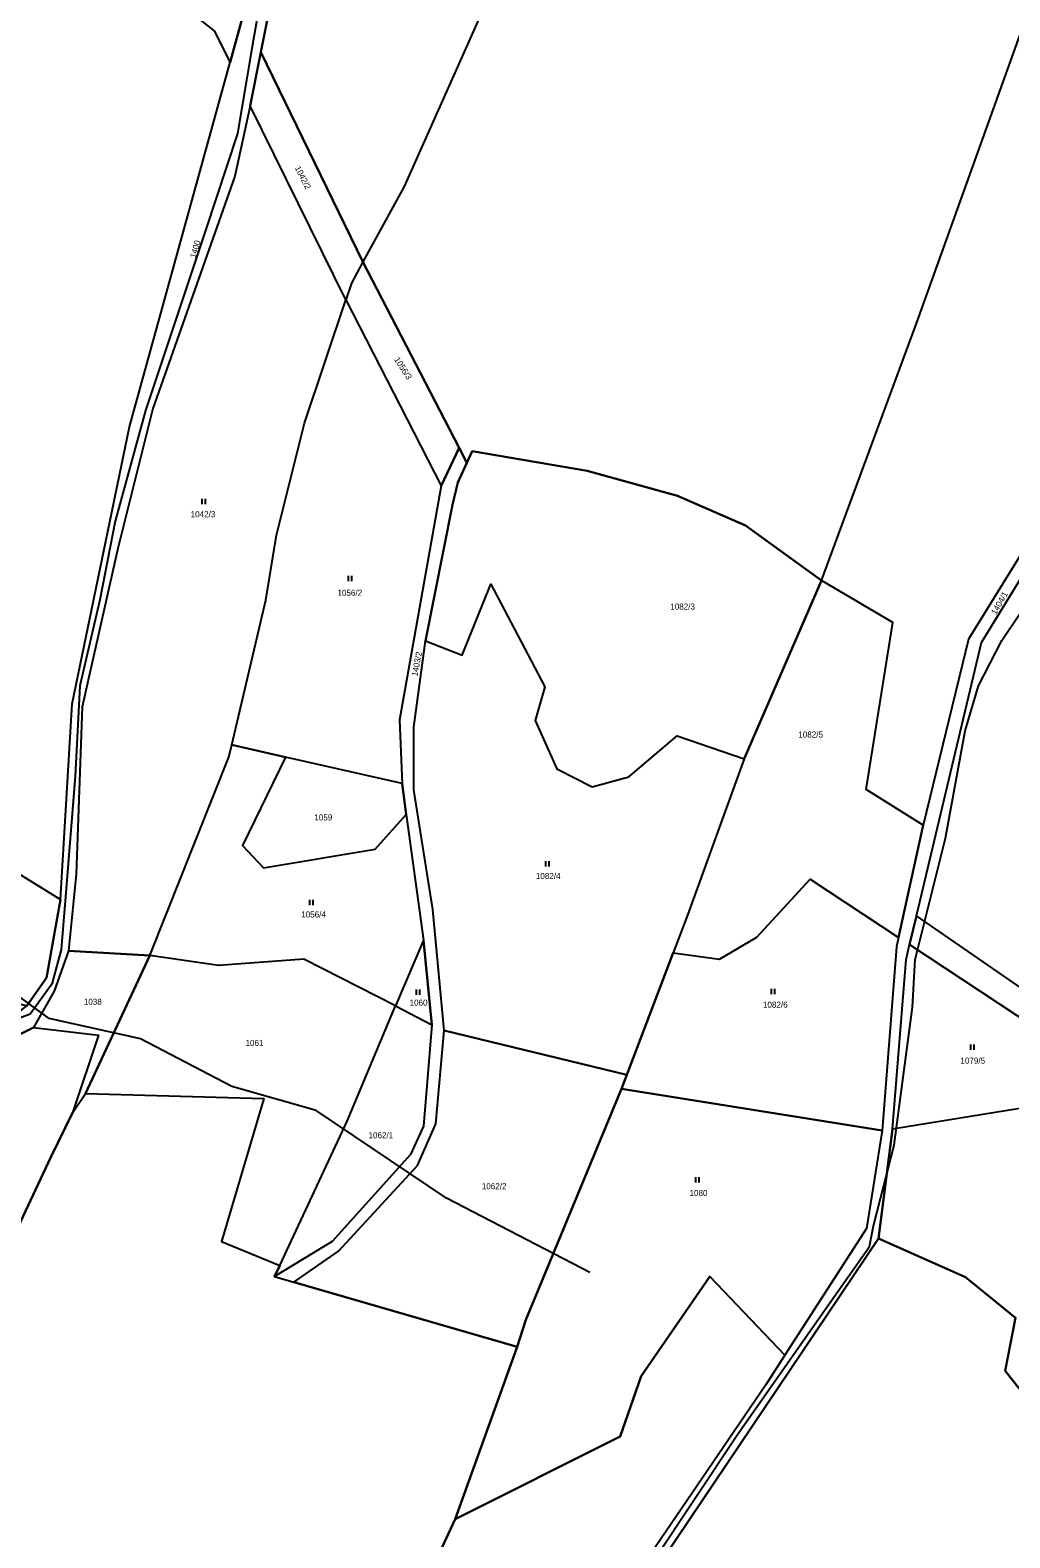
# Model space of a CAD drawing. Extents: x -588699 to -585793, y -1060280 to -1056731.
# Drawn here: x -588096.7 to -587820.9, y -1059020.2 to -1058596 of the extents above; entities that cross this region are included whole.
import ezdxf

# ---------------------------------------------------------------- set-up
doc = ezdxf.new("R2010")
doc.units = 0
for name, color, linetype in [('Druh pozemku', 7, 'Continuous'), ('Parcela nároku', 7, 'Continuous'), ('Vnitřní obvod', 7, 'Continuous'), ('Vnější obvod_k šeření', 7, 'Continuous')]:
    doc.layers.add(name, color=color, linetype=linetype)

msp = doc.modelspace()

# ---------------------------------------------------------------- linework, layer by layer
at = {"layer": 'Druh pozemku'}
for p, q in [((-588048.34, -1058727.85), (-588048.34, -1058729.35)), ((-588047.32, -1058729.35), (-588047.32, -1058727.85)), ((-588007.19, -1058749.54), (-588007.19, -1058751.04)), ((-588006.17, -1058751.04), (-588006.17, -1058749.54)), ((-587951.59, -1058829.77), (-587951.59, -1058831.27)), ((-587950.57, -1058831.27), (-587950.57, -1058829.77)), ((-588018.07, -1058840.65), (-588018.07, -1058842.15)), ((-588017.05, -1058842.15), (-588017.05, -1058840.65)), ((-587988.03, -1058865.91), (-587988.03, -1058867.41)), ((-587987.01, -1058867.41), (-587987.01, -1058865.91)), ((-587888.08, -1058865.71), (-587888.08, -1058867.21)), ((-587887.06, -1058867.21), (-587887.06, -1058865.71)), ((-587832, -1058881.34), (-587832, -1058882.84)), ((-587830.97, -1058882.84), (-587830.97, -1058881.34)), ((-587909.41, -1058918.67), (-587909.41, -1058920.17)), ((-587908.39, -1058920.17), (-587908.39, -1058918.67))]:
    msp.add_line(p, q, dxfattribs=at)
at = {"layer": 'Parcela nároku'}
for points in [[(-588012.84, -1058544.25), (-587965.05, -1058467.76), (-587942.29, -1058493.44), (-587956.18, -1058550.14), (-587968.29, -1058588.22), (-587991.4, -1058639.93), (-588003.03, -1058661.2), (-588031.77, -1058602.2), (-588025, -1058568.22)], [(-588109.84, -1058534.93), (-588036.79, -1058592.04), (-588040.36, -1058604.95), (-588044.66, -1058596.24), (-588112.84, -1058542.38)], [(-588189.32, -1058742.9), (-588190.21, -1058759.8), (-588172.56, -1058777.54), (-588159.73, -1058806.34), (-588132.18, -1058821.5), (-588109.1, -1058827.66), (-588088.15, -1058840.59), (-588084.85, -1058785.48), (-588068.73, -1058707.6), (-588040.36, -1058604.95), (-588044.66, -1058596.24), (-588112.84, -1058542.38), (-588131.02, -1058585.83), (-588144.44, -1058606.7), (-588168.14, -1058675.06)], [(-588031.77, -1058602.2), (-588003.03, -1058661.2), (-588006.27, -1058667.12), (-588007.86, -1058671.88), (-588034.7, -1058617.24)], [(-588072.03, -1058741.84), (-588082.04, -1058786.35), (-588083.73, -1058833.41), (-588085.9, -1058855), (-588062.96, -1058856.3), (-588040.73, -1058800.53), (-588039.91, -1058797.03), (-588030.34, -1058756.33), (-588027.37, -1058738.07), (-588019.46, -1058706.56), (-588007.86, -1058671.88), (-588034.7, -1058617.24), (-588039.05, -1058637.03), (-588062.18, -1058702.41)], [(-587975.92, -1058713.52), (-588003.03, -1058661.2), (-588006.27, -1058667.12), (-588007.86, -1058671.88), (-587980.98, -1058724.18)], [(-588019.46, -1058706.56), (-588007.86, -1058671.88), (-587980.98, -1058724.18), (-587992.71, -1058790.06), (-587992, -1058807.94), (-588024.76, -1058800.48), (-588039.91, -1058797.03), (-588030.34, -1058756.33), (-588027.37, -1058738.07)], [(-587983.65, -1058875.79), (-587985.94, -1058904.34), (-587989.61, -1058912.34), (-588011.67, -1058936.8), (-588027.86, -1058946.66), (-588022.46, -1058948.22), (-588009.91, -1058939.54), (-587987.63, -1058915.45), (-587982.53, -1058903.73), (-587980.17, -1058877.47), (-587983.38, -1058843.42), (-587988.72, -1058809.72), (-587988.72, -1058792.06), (-587985.38, -1058767.81), (-587977.81, -1058729.55), (-587976.33, -1058723.23), (-587973.78, -1058717.71), (-587975.92, -1058713.52), (-587980.98, -1058724.18), (-587992.71, -1058790.06), (-587992, -1058807.94), (-587990.81, -1058816.7), (-587986.01, -1058851.97)], [(-587914.45, -1058726.97), (-587939.88, -1058719.94), (-587972.25, -1058714.41), (-587973.78, -1058717.71), (-587976.33, -1058723.23), (-587977.81, -1058729.55), (-587985.38, -1058767.81), (-587975.04, -1058771.83), (-587967.02, -1058751.85), (-587951.78, -1058780.74), (-587954.54, -1058790.2), (-587948.48, -1058803.84), (-587938.5, -1058808.83), (-587928.16, -1058806.07), (-587914.61, -1058794.48), (-587895.71, -1058801.01), (-587873.98, -1058750.77), (-587895.32, -1058735.33)], [(-587954.54, -1058790.2), (-587948.48, -1058803.84), (-587938.5, -1058808.83), (-587928.16, -1058806.07), (-587914.61, -1058794.48), (-587895.71, -1058801.01), (-587911.64, -1058844.95), (-587915.68, -1058855.57), (-587928.74, -1058889.95), (-587980.17, -1058877.47), (-587983.38, -1058843.42), (-587988.72, -1058809.72), (-587988.72, -1058792.06), (-587985.38, -1058767.81), (-587975.04, -1058771.83), (-587967.02, -1058751.85), (-587951.78, -1058780.74)], [(-587853.86, -1058762.63), (-587873.98, -1058750.77), (-587895.71, -1058801.01), (-587911.64, -1058844.95), (-587915.68, -1058855.57), (-587902.69, -1058857.39), (-587892.19, -1058851.17), (-587877.15, -1058834.81), (-587852.25, -1058851.24), (-587845.33, -1058819.66), (-587861.34, -1058809.6)], [(-588109.1, -1058827.66), (-588088.15, -1058840.59), (-588092.07, -1058862.61), (-588097.6, -1058870.46), (-588109.72, -1058867.96), (-588143.59, -1058855.75), (-588178.69, -1058824), (-588198.5, -1058806.08), (-588211.07, -1058801.26), (-588191.27, -1058761.91), (-588190.21, -1058759.8), (-588172.56, -1058777.54), (-588159.73, -1058806.34), (-588132.18, -1058821.5)], [(-587990.81, -1058816.7), (-587986.01, -1058851.97), (-587993.87, -1058870.52), (-588019.67, -1058857.36), (-588043.64, -1058859.15), (-588062.96, -1058856.3), (-588040.73, -1058800.53), (-588039.91, -1058797.03), (-588024.76, -1058800.48), (-588036.89, -1058825.37), (-588031.03, -1058831.68), (-587999.58, -1058826.39)], [(-587990.81, -1058816.7), (-587992, -1058807.94), (-588024.76, -1058800.48), (-588036.89, -1058825.37), (-588031.03, -1058831.68), (-587999.58, -1058826.39)], [(-587930.23, -1058893.88), (-587928.74, -1058889.95), (-587915.68, -1058855.57), (-587902.69, -1058857.39), (-587892.19, -1058851.17), (-587877.15, -1058834.81), (-587852.25, -1058851.24), (-587852.87, -1058853.92), (-587856.9, -1058905.55)], [(-587804.58, -1058874.64), (-587847.22, -1058845.13), (-587849.15, -1058853.28), (-587804.12, -1058882.99), (-587796.78, -1058895.87), (-587776.67, -1058931.16), (-587774.83, -1058926.17)], [(-588085.9, -1058855), (-588089.94, -1058866.37), (-588095.73, -1058876.62), (-588077.46, -1058878.76), (-588084.75, -1058900.64), (-588081.07, -1058895.13), (-588062.96, -1058856.3)], [(-587986.01, -1058851.97), (-587993.87, -1058870.52), (-587983.65, -1058875.79)], [(-587849.15, -1058853.28), (-587804.12, -1058882.99), (-587796.78, -1058895.87), (-587853.95, -1058905.21), (-587850.15, -1058857.49)], [(-588043.64, -1058859.15), (-588062.96, -1058856.3), (-588081.07, -1058895.13), (-588030.89, -1058896.53), (-588042.81, -1058936.79), (-588026.41, -1058943.57), (-588007.44, -1058902.96), (-587993.87, -1058870.52), (-588019.67, -1058857.36)], [(-587993.87, -1058870.52), (-587983.65, -1058875.79), (-587985.94, -1058904.34), (-587989.61, -1058912.34), (-588011.67, -1058936.8), (-588027.86, -1058946.66), (-588026.41, -1058943.57), (-588007.44, -1058902.96)], [(-587982.53, -1058903.73), (-587980.17, -1058877.47), (-587928.74, -1058889.95), (-587930.23, -1058893.88), (-587957.2, -1058958.88), (-587959.61, -1058966.41), (-588022.46, -1058948.22), (-588009.91, -1058939.54), (-587987.63, -1058915.45)], [(-587977.01, -1059014.9), (-587959.61, -1058966.41), (-587957.2, -1058958.88), (-587930.23, -1058893.88), (-587856.9, -1058905.55), (-587861.28, -1058933.17), (-587884.31, -1058968.74), (-587905.4, -1058946.63), (-587924.68, -1058974.72), (-587930.6, -1058991.62)], [(-587789.32, -1058964.36), (-587792.22, -1058963.13), (-587801.94, -1058917.76), (-587796.24, -1058906.14), (-587796.78, -1058895.87), (-587853.95, -1058905.21), (-587857.94, -1058935.91), (-587833.41, -1058946.87), (-587819.38, -1058958.28), (-587822.27, -1058973.22), (-587812.23, -1058985.89), (-587800.01, -1058977.56), (-587794.76, -1058980.28)], [(-587800.01, -1058977.56), (-587812.23, -1058985.89), (-587822.27, -1058973.22), (-587819.38, -1058958.28), (-587833.41, -1058946.87), (-587857.94, -1058935.91), (-587921.85, -1059031.04), (-587985.54, -1059125.5), (-587999.42, -1059164.21), (-587980.79, -1059164.61), (-587966.55, -1059169.47), (-587944.72, -1059179.02), (-587897.85, -1059200.19), (-587902.23, -1059213.76), (-587896.62, -1059200.63), (-587881.71, -1059163.96), (-587839.09, -1059080.55), (-587819.95, -1059037.06), (-587810.06, -1059008.37), (-587794.76, -1058980.28)], [(-587924.68, -1058974.72), (-587905.4, -1058946.63), (-587884.31, -1058968.74), (-587889.64, -1058977.16), (-587988.8, -1059122.67), (-588002.41, -1059162.6), (-588025.52, -1059154.45), (-588014.35, -1059123.9), (-588019.76, -1059121.36), (-588002.33, -1059069.22), (-587977.01, -1059014.9), (-587930.6, -1058991.62)]]:
    msp.add_lwpolyline(points, close=True, dxfattribs=at)
for points in [[(-587968.29, -1058588.22), (-587991.4, -1058639.93), (-588003.03, -1058661.2), (-587975.92, -1058713.52), (-587973.78, -1058717.71), (-587972.25, -1058714.41), (-587939.88, -1058719.94), (-587914.45, -1058726.97), (-587895.32, -1058735.33), (-587873.98, -1058750.77), (-587847.1, -1058678.18), (-587805.8, -1058562.87)], [(-587812.7, -1058735.14), (-587832.62, -1058767.34), (-587845.33, -1058819.66), (-587861.34, -1058809.6), (-587853.86, -1058762.63), (-587873.98, -1058750.77), (-587847.1, -1058678.18), (-587805.8, -1058562.87)], [(-588025, -1058568.22), (-588031.77, -1058602.2), (-588034.7, -1058617.24), (-588039.05, -1058637.03), (-588062.18, -1058702.41), (-588072.03, -1058741.84), (-588082.04, -1058786.35), (-588083.73, -1058833.41), (-588085.9, -1058855), (-588089.94, -1058866.37), (-588095.73, -1058876.62), (-588107.01, -1058882.12), (-588126.45, -1058892.22), (-588165.98, -1058898.34), (-588183.08, -1058904.53), (-588195.69, -1058915.39), (-588216.39, -1058945.62), (-588238.98, -1058997.37), (-588255.65, -1059039.32)], [(-588258.73, -1059039.66), (-588238.76, -1058986.59), (-588219.68, -1058943.58), (-588198.82, -1058912.69), (-588184.27, -1058901.04), (-588168.91, -1058895.22), (-588129.14, -1058889.4), (-588109.09, -1058879.61), (-588097.6, -1058870.46), (-588092.07, -1058862.61), (-588088.15, -1058840.59), (-588084.85, -1058785.48), (-588068.73, -1058707.6), (-588040.36, -1058604.95), (-588036.79, -1058592.04)], [(-587812.7, -1058735.14), (-587832.62, -1058767.34), (-587845.33, -1058819.66), (-587852.25, -1058851.24), (-587852.87, -1058853.92), (-587856.9, -1058905.55), (-587861.28, -1058933.17), (-587884.31, -1058968.74), (-587889.64, -1058977.16), (-587988.8, -1059122.67)], [(-587921.85, -1059031.04), (-587857.94, -1058935.91), (-587853.95, -1058905.21), (-587850.15, -1058857.49), (-587849.15, -1058853.28), (-587847.22, -1058845.13), (-587828.97, -1058768.29), (-587810.6, -1058738.41)], [(-587804.58, -1058874.64), (-587847.22, -1058845.13), (-587828.97, -1058768.29), (-587810.6, -1058738.41)], [(-588255.65, -1059039.32), (-588238.98, -1058997.37), (-588216.39, -1058945.62), (-588195.69, -1058915.39), (-588183.08, -1058904.53), (-588143.39, -1058900.22), (-588125.37, -1058896.06), (-588107.01, -1058882.12), (-588095.73, -1058876.62), (-588077.46, -1058878.76), (-588084.75, -1058900.64), (-588090.88, -1058913.09), (-588105.81, -1058944.86), (-588128.61, -1058976.17), (-588138.56, -1058991.29), (-588140.31, -1058990.53), (-588157.68, -1059017.89), (-588153.56, -1059020.13), (-588159.61, -1059038.12)], [(-588159.61, -1059038.12), (-588153.56, -1059020.13), (-588145.27, -1059016.64), (-588133.67, -1058993.19), (-588138.56, -1058991.29), (-588128.61, -1058976.17), (-588105.81, -1058944.86), (-588090.88, -1058913.09), (-588084.75, -1058900.64), (-588081.07, -1058895.13), (-588030.89, -1058896.53), (-588042.81, -1058936.79), (-588026.41, -1058943.57), (-588027.86, -1058946.66), (-588022.46, -1058948.22), (-587959.61, -1058966.41), (-587977.01, -1059014.9), (-588002.33, -1059069.22)]]:
    msp.add_lwpolyline(points, dxfattribs=at)
at = {"layer": 'Vnitřní obvod'}
for points in [[(-588030.66, -1058580.1), (-588034.23, -1058601.15), (-588038.28, -1058625.03), (-588047.25, -1058652.04), (-588056.22, -1058679.05), (-588064.16, -1058702.97), (-588072.73, -1058734.12), (-588077.04, -1058756.27), (-588082.66, -1058780.45), (-588084.04, -1058805.86), (-588086.73, -1058839.81), (-588087.91, -1058854.64), (-588090.56, -1058864.4), (-588096.66, -1058872.79), (-588109.2, -1058877.51), (-588140.38, -1058882.97), (-588166.6, -1058884.83), (-588184.84, -1058889.82), (-588197.09, -1058901.79), (-588209.48, -1058925.73), (-588229.29, -1058960.64), (-588240.97, -1058989), (-588253.58, -1059028.11)], [(-587945.03, -1059062.5), (-587897.58, -1058991.12), (-587876.68, -1058961.32), (-587860.47, -1058938.2), (-587859.31, -1058932.38), (-587853.53, -1058909.66), (-587848.3, -1058870.87), (-587847.58, -1058857.44), (-587844.4, -1058844.74), (-587839.04, -1058823.35), (-587833.52, -1058793.13), (-587829.78, -1058780.5), (-587823.2, -1058767.71), (-587808.06, -1058745.23)]]:
    msp.add_lwpolyline(points, dxfattribs=at)
at = {"layer": 'Vnější obvod_k šeření'}
msp.add_lwpolyline([(-587939.19, -1058945.49), (-587979.52, -1058924.6), (-588016.13, -1058899.95), (-588039.93, -1058893.15), (-588065.62, -1058879.81), (-588091.31, -1058874.05), (-588100.79, -1058867.12)], dxfattribs=at)

# ---------------------------------------------------------------- texts
at = {"layer": 'Parcela nároku'}
for s, rotation, p in [('1042/2', 297.1577, (-588022.24, -1058634.74)), ('1400', 73.0837, (-588050.11, -1058660.25)), ('1056/3', 302.8526, (-587994.3, -1058688.64)), ('1404/1', 60.2943, (-587824.86, -1058760.6)), ('1403/2', 78.9997, (-587987.69, -1058777.87))]:
    msp.add_text(s, height=1.7, rotation=rotation, dxfattribs=at).set_placement(p)
for s, p in [('1042/3', (-588051.5, -1058733)), ('1056/2', (-588010.18, -1058755.13)), ('1082/3', (-587916.52, -1058759)), ('1082/5', (-587880.48, -1058795)), ('1059', (-588016.68, -1058818.33)), ('1082/4', (-587954.34, -1058834.8)), ('1056/4', (-588020.39, -1058845.63)), ('1038', (-588081.55, -1058870.2)), ('1060', (-587989.88, -1058870.43)), ('1082/6', (-587890.44, -1058871)), ('1061', (-588036.06, -1058881.77)), ('1079/5', (-587834.87, -1058886.75)), ('1062/1', (-588001.44, -1058907.75)), ('1062/2', (-587969.55, -1058922.09)), ('1080', (-587911.1, -1058924))]:
    msp.add_text(s, height=1.7, dxfattribs=at).set_placement(p)

doc.saveas('drawing.dxf')
